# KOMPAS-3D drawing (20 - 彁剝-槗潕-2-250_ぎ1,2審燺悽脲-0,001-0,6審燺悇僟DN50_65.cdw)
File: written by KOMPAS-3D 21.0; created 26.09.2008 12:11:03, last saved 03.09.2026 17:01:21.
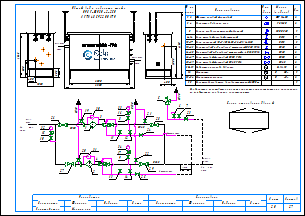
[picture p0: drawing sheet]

Sheets 1-2: A3, landscape

Document properties: Наименование: Макро:21; Автор: RaskoAdmin; Форматы листов документа: 2xA3; Полное имя файла: \\UR38nt01\Departments\КТО\КБ ПУРДГ\Заявки\Прайс-лист на типовые шкафы ГРПШ\ПРДГ_стандарт_20_03_2026\ПРДГ с РДГ(Н, В)\ПРДГ-ШУЭО-2-250_до1,2МПа_Рвых-0,001-0,6МПа_РДГ_DN50_65.cdw

Title block, sheet 1: Наименование: Пункт учета газа / ПУГ-Ш-400-Р / ЛГТИ.485922.001ТУ; designation: ЛГТИ.03.4411141; sheet number: 1; Количество листов документа: 2; organisation: ООО "ЭЛЬСТЕР Газэлектроника"; Форматы листов документа: A3; stored path: C:\Рабочие документы\Компас\ПУГ\Схема.cdw; Разработал: Устинов; Проверил: Кошкин; Утвердил: Кошкин
Title block, sheet 2: sheet number: 2; stored path: D:\Рабочие документы\Заявки\ПУРДГ\ПУРДГ-ШУЭО-2-100-Р 4411220.cdw; designation, second copy: ЛГТИ.03.4411141-

Views: Вид 1, Вид 2
Referenced files: wcvoit.frw
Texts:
  Normal
  № на
  схеме
  Усл.
  обозн.
  Марка
  (модель)
  Кол.
  Фильтр газовый фланцевый
  ФГ 16-50
  Регулятор давления газа
  РДГ-50
  Клапан предохранительный сбросной
  КПС DN20
  Кран шаровой газовый латунный
  DN15
  Кран кнопочный VE-РАСКО-НЗ-1,6-G1/2-М20
  Кран шаровой "под приварку" штуцерный DN20 PN16
  Кран шаровой "под приварку" штуцерный п/п DN20 PN16
  DN20
  Кран шаровой фланцевый DN50 PN16
  Кран шаровой фланцевый DN65 PN16
  DN50
  DN65
  Индикатор перепада давления
  Delta 15
  Манометр
  Манометр-напоромер
  Электрообогреватель взрывозащищенный 600Вт
  0...     МПа
  0...     кПа
  Общий вид и габариты шкафа
  ПРДГ-ШУЭО-2-250
  Выход газа
  Вход газа
  logo-rasko-ge.png
  Вход
  газа
  PDI
  Выход
  Р=     кПа
  Импульс DN20
  ≥5DN
  HYSWLongFangSong
  Р=       МПа
  Схема открывания дверей
  Предприятие изготовитель может заменять комплектующие на аналогичные,
  не ухудшающие заявленных характеристик.
  Должность
  Конструктор
  Фамилия
  Подпись
  Дата
  Согласовано
  Максимкин
  Лист
  Листов
  POLYLINE_STYLE_0.18_RGB_0_0_0
  POLYLINE_STYLE_0.50_RGB_0_0_0
  POLYLINE_STYLE_0.34_RGB_0_0_0
  PHANTOM_RGB_0_0_0_SC_1_THICK_0.18
  K5LT_THIN_RGB_0_0_0_THICK_0.18
  K5LT32769_RGB_0_0_0_THICK_0.18
  K5LT12_RGB_0_0_0_SC_1_THICK_0.18
  K5LT_DASHED_RGB_0_0_0_SC_1_THICK_0.18
  ACISOTGL_RGB_0_0_0_SC_0.8_THICK_0.25
  CONTINUOUS_RGB_0_127_31_THICK_0.3
  CONTINUOUS_RGB_0_0_255_THICK_0.35
  CONTINUOUS_RGB_255_0_0_THICK_0.35
  POLYLINE_STYLE_0.25_RGB_0_0_0
  CONTINUOUS_RGB_0_0_0_THICK_0.5
  POLYLINE_STYLE_0.35_RGB_0_0_255
  CONTINUOUS_RGB_0_0_0_THICK_0.4
  CONTINUOUS_RGB_0_0_0_THICK_0.35
  Без оформления
Dimensions and other numbers on the sheet: 1; 1, 2; 2; 3, 4; 5; 6-14; 9; 15-17; 3; 18-23; 24-25; 6; 26-27; 28-29; 30-31; 32; 33-34; 35; 400; 1050; 500; 305; 1565; 2800; 1000; 4130; 2500; 4; 10; 27; 28; 29; 23; 8; 12; 19; 20; 21; 22; 25; 24; 30; 31; 15; 16; 26; 7; 11; 14; 13; 33; 17; 34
